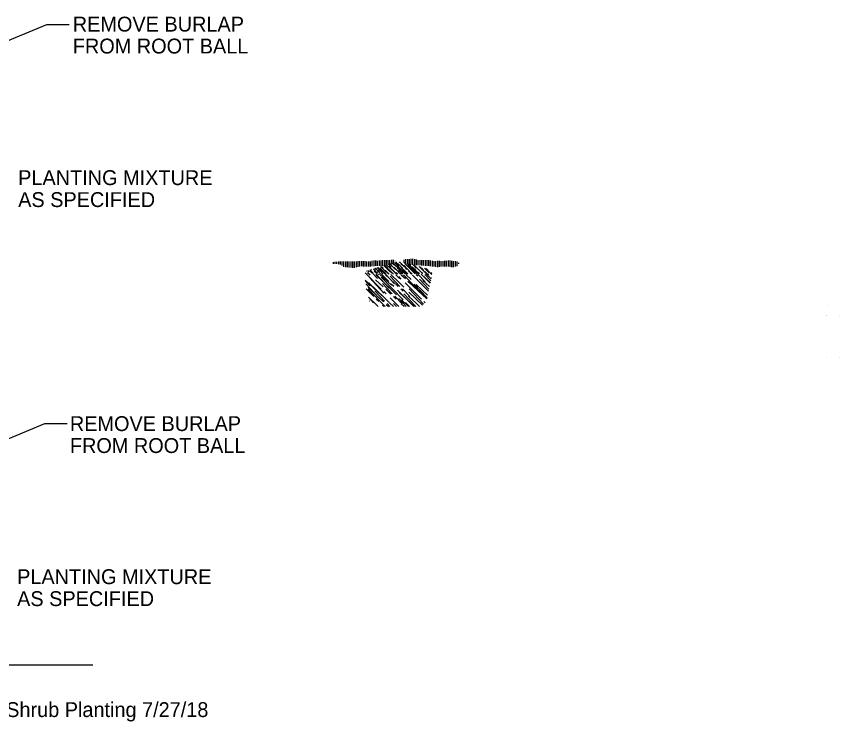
# Model space of a CAD drawing. Extents: x 10082 to 10186, y 10014 to 10052.
# Drawn here: x 10147.41 to 10186.18, y 10014.37 to 10047.58 of the extents above; entities that cross this region are included whole.
import ezdxf

# ---------------------------------------------------------------- set-up
doc = ezdxf.new("R2010")
doc.units = 0
for name, color, linetype in [('Default', 7, 'Continuous'), ('G-ANNO-CELL', 7, 'Continuous'), ('G-ANNO-TEXT', 7, 'Continuous'), ('G-DETL-TEXT', 7, 'Continuous')]:
    doc.layers.add(name, color=color, linetype=linetype)

# ---------------------------------------------------------------- blocks, each defined once
blk = doc.blocks.new('POINT_DISPLAY')
at = {"layer": 'Default'}
blk.add_line((0, 0), (0, 0), dxfattribs=at)
blk = doc.blocks.new('_X3')
at = {"layer": 'Default'}
for p, q in [((2.0243, 1.2759), (2.0002, 1.3001)), ((2.0038, 1.3007), (2.0077, 1.2971)), ((2.0067, 1.2931), (2.0283, 1.2699)), ((2.0187, 1.2918), (2.0118, 1.2989)), ((2.0159, 1.2987), (2.036, 1.2771)), ((2.0394, 1.2747), (2.0166, 1.2967)), ((2.0196, 1.2985), (2.0203, 1.2977)), ((2.0396, 1.2817), (2.0218, 1.2983)), ((2.024, 1.2939), (2.0571, 1.2597)), ((2.0355, 1.2872), (2.0245, 1.2982)), ((2.0301, 1.2979), (2.0378, 1.2907)), ((2.0312, 1.2978), (2.0438, 1.2843)), ((2.0521, 1.2799), (2.0374, 1.2952)), ((2.0504, 1.2861), (2.0386, 1.2975)), ((2.0462, 1.2973), (2.0515, 1.2916)), ((2.0542, 1.2909), (2.0505, 1.2947)), ((2.054, 1.2972), (2.054, 1.2973)), ((2.0541, 1.2973), (2.0603, 1.2915)), ((2.0636, 1.291), (2.0574, 1.2973)), ((2.0575, 1.2973), (2.0761, 1.2781)), ((2.0691, 1.2902), (2.0616, 1.2974)), ((2.0949, 1.2727), (2.0711, 1.2965)), ((2.0766, 1.2979), (2.0788, 1.2959)), ((2.0897, 1.2868), (2.0788, 1.2981)), ((2.0977, 1.2854), (2.0838, 1.2984)), ((2.0975, 1.2848), (2.0877, 1.2942)), ((2.0892, 1.2977), (2.0982, 1.288)), ((2.0989, 1.2911), (2.0913, 1.2988)), ((2.0928, 1.2989), (2.0951, 1.2964)), ((2.0974, 1.3003), (2.0999, 1.298)), ((2.0999, 1.2991), (2.0982, 1.3008)), ((2.0988, 1.2926), (2.0992, 1.2923)), ((2.0252, 1.2662), (2.0003, 1.2894)), ((2.0073, 1.2807), (2.0005, 1.2877)), ((2.001, 1.2837), (2.0206, 1.2627)), ((2.0284, 1.2633), (2.0055, 1.2853)), ((2.0154, 1.2899), (2.027, 1.2791)), ((2.0407, 1.2689), (2.026, 1.2841)), ((2.043, 1.2797), (2.0393, 1.2834)), ((2.0417, 1.2871), (2.0494, 1.2799)), ((2.0581, 1.2788), (2.0504, 1.2861)), ((2.0842, 1.261), (2.0598, 1.2853)), ((2.0641, 1.2879), (2.068, 1.2843)), ((2.0924, 1.2614), (2.0656, 1.2864)), ((2.0783, 1.2757), (2.0672, 1.2872)), ((2.0737, 1.2833), (2.0927, 1.2629)), ((2.0935, 1.2666), (2.0767, 1.2828)), ((2.0814, 1.2905), (2.0955, 1.2755)), ((2.0866, 1.2886), (2.0964, 1.2795)), ((2.0131, 1.2647), (2.0018, 1.276)), ((2.0046, 1.2783), (2.0162, 1.2675)), ((2.0049, 1.2756), (2.0299, 1.2497)), ((2.0293, 1.2579), (2.0146, 1.2731)), ((2.0318, 1.2685), (2.028, 1.2722)), ((2.0309, 1.2755), (2.0386, 1.2683)), ((2.047, 1.2673), (2.0394, 1.2747)), ((2.0729, 1.2498), (2.0486, 1.2741)), ((2.0738, 1.2498), (2.0512, 1.2709)), ((2.0533, 1.2763), (2.0572, 1.2726)), ((2.0669, 1.2647), (2.0558, 1.2761)), ((2.0582, 1.2689), (2.076, 1.2498)), ((2.086, 1.2518), (2.0657, 1.2714)), ((2.066, 1.2761), (2.0874, 1.2531)), ((2.0758, 1.277), (2.0874, 1.2662)), ((2.0798, 1.2743), (2.0923, 1.2612)), ((2.0923, 1.2612), (2.0856, 1.2681)), ((2.005, 1.2639), (2.0128, 1.2555)), ((2.0174, 1.2519), (2.005, 1.2638)), ((2.0073, 1.2578), (2.0069, 1.2583)), ((2.0206, 1.2572), (2.0168, 1.261)), ((2.0201, 1.2639), (2.0278, 1.2566)), ((2.036, 1.2559), (2.0284, 1.2633)), ((2.0505, 1.2498), (2.0374, 1.2628)), ((2.0425, 1.2646), (2.0464, 1.261)), ((2.0554, 1.2537), (2.0444, 1.2651)), ((2.0505, 1.2616), (2.0615, 1.2498)), ((2.0652, 1.2498), (2.0546, 1.26)), ((2.0607, 1.2559), (2.0666, 1.2498)), ((2.0649, 1.2654), (2.0765, 1.2546)), ((2.0812, 1.2499), (2.0742, 1.2571)), ((2.0897, 1.2554), (2.0879, 1.2572)), ((2.0912, 1.2626), (2.0924, 1.2615)), ((2.0196, 1.2497), (2.0174, 1.2519)), ((2.0281, 1.2497), (2.0262, 1.2516)), ((2.0317, 1.253), (2.0352, 1.2497)), ((2.0372, 1.2497), (2.033, 1.2541)), ((2.0428, 1.2497), (2.0368, 1.2554)), ((2.0427, 1.2544), (2.0471, 1.2498)), ((2.0541, 1.2538), (2.0584, 1.2498)), ((2.0804, 1.251), (2.0816, 1.2499))]:
    blk.add_line(p, q, dxfattribs=at)
blk = doc.blocks.new('_X2')
at = {"layer": 'Default'}
for p, q in [((2.0585, 1.3154), (2.0585, 1.3196)), ((2.0611, 1.3149), (2.0611, 1.3205)), ((2.0638, 1.3143), (2.0638, 1.3207)), ((2.0664, 1.3134), (2.0664, 1.3208)), ((2.069, 1.3127), (2.069, 1.3209)), ((2.0717, 1.3123), (2.0717, 1.321)), ((2.0743, 1.3119), (2.0743, 1.3205)), ((2.077, 1.3115), (2.077, 1.3199)), ((2.0796, 1.3115), (2.0796, 1.3193)), ((2.0823, 1.3115), (2.0823, 1.319)), ((2.0849, 1.3113), (2.0849, 1.3191)), ((2.0876, 1.3111), (2.0876, 1.3192)), ((2.0902, 1.3108), (2.0902, 1.3193)), ((2.0929, 1.3106), (2.0929, 1.3191)), ((2.0955, 1.3104), (2.0955, 1.319)), ((2.0981, 1.3101), (2.0981, 1.3186)), ((2.1008, 1.3098), (2.1008, 1.318)), ((2.1034, 1.3095), (2.1034, 1.3175)), ((2.1061, 1.3091), (2.1061, 1.3178)), ((2.1087, 1.3088), (2.1087, 1.3181)), ((2.1114, 1.3091), (2.1114, 1.3181)), ((2.114, 1.3097), (2.114, 1.3178)), ((2.1167, 1.3098), (2.1167, 1.3175)), ((2.1193, 1.3098), (2.1193, 1.3179)), ((2.122, 1.3098), (2.122, 1.3183)), ((2.1246, 1.3097), (2.1246, 1.3186)), ((2.1273, 1.3092), (2.1273, 1.3184)), ((2.1299, 1.3087), (2.1299, 1.3183)), ((2.1325, 1.3086), (2.1325, 1.3178)), ((2.1352, 1.3094), (2.1352, 1.3174)), ((2.1378, 1.3103), (2.1378, 1.317)), ((2.1405, 1.3135), (2.1405, 1.3151))]:
    blk.add_line(p, q, dxfattribs=at)
blk = doc.blocks.new('_X1')
at = {"layer": 'Default'}
for p, q in [((1.9632, 1.3126), (1.9632, 1.3172)), ((1.9659, 1.3109), (1.9659, 1.3172)), ((1.9685, 1.309), (1.9685, 1.3172)), ((1.9711, 1.3086), (1.9711, 1.3172)), ((1.9844, 1.3078), (1.9844, 1.3172)), ((1.987, 1.3085), (1.987, 1.3173)), ((1.9897, 1.3091), (1.9897, 1.3175)), ((1.9923, 1.3098), (1.9923, 1.3175)), ((1.995, 1.31), (1.995, 1.3175)), ((1.9976, 1.3097), (1.9976, 1.3175)), ((2.0003, 1.3095), (2.0003, 1.3174)), ((2.0029, 1.3095), (2.0029, 1.3173)), ((2.0055, 1.3096), (2.0055, 1.3173)), ((2.0082, 1.3097), (2.0082, 1.3172)), ((2.0108, 1.31), (2.0108, 1.3179)), ((2.0135, 1.3103), (2.0135, 1.3185)), ((2.0161, 1.3106), (2.0161, 1.3185)), ((2.0188, 1.3107), (2.0188, 1.3183)), ((2.0214, 1.3104), (2.0214, 1.3184)), ((2.0241, 1.3101), (2.0241, 1.3186)), ((2.0267, 1.3108), (2.0267, 1.3189)), ((2.0294, 1.3115), (2.0294, 1.3192)), ((2.032, 1.312), (2.032, 1.3191)), ((2.0346, 1.3125), (2.0346, 1.319)), ((2.0373, 1.3129), (2.0373, 1.3192)), ((2.0399, 1.3141), (2.0399, 1.3197)), ((2.0426, 1.3153), (2.0426, 1.3195)), ((2.0452, 1.3178), (2.0452, 1.3183)), ((1.9526, 1.3137), (1.9526, 1.3163)), ((1.9553, 1.3137), (1.9553, 1.3165)), ((1.9579, 1.3135), (1.9579, 1.3167)), ((1.9606, 1.313), (1.9606, 1.3169)), ((1.9738, 1.3084), (1.9738, 1.3171)), ((1.9764, 1.3082), (1.9764, 1.317)), ((1.9791, 1.308), (1.9791, 1.3169)), ((1.9817, 1.3078), (1.9817, 1.317))]:
    blk.add_line(p, q, dxfattribs=at)
blk = doc.blocks.new('_X0')
at = {"layer": 'Default'}
for p, q in [((0.6297, 0.3389), (0.6229, 0.3453)), ((0.6231, 0.345), (0.6397, 0.3279)), ((0.6263, 0.3442), (0.6249, 0.3455)), ((0.6256, 0.3456), (0.6259, 0.3452)), ((0.63, 0.346), (0.6307, 0.3454)), ((0.638, 0.3386), (0.6306, 0.346)), ((0.641, 0.3417), (0.6376, 0.3452)), ((0.5815, 0.3323), (0.5811, 0.3327)), ((0.5851, 0.331), (0.583, 0.3332)), ((0.5911, 0.3294), (0.5862, 0.3342)), ((0.5862, 0.3326), (0.5894, 0.3296)), ((0.5887, 0.3338), (0.5877, 0.3347)), ((0.5941, 0.3332), (0.5915, 0.3358)), ((0.5918, 0.3352), (0.5978, 0.3288)), ((0.5964, 0.3289), (0.5928, 0.3324)), ((0.5936, 0.3365), (0.5955, 0.3348)), ((0.5944, 0.3367), (0.6023, 0.3285)), ((0.5968, 0.3349), (0.5949, 0.3368)), ((0.597, 0.3375), (0.6056, 0.3282)), ((0.5974, 0.333), (0.5993, 0.3312)), ((0.6087, 0.3281), (0.5985, 0.3379)), ((0.6006, 0.3311), (0.5987, 0.333)), ((0.6072, 0.3311), (0.6016, 0.3368)), ((0.6104, 0.328), (0.6017, 0.3361)), ((0.6026, 0.3392), (0.6104, 0.3308)), ((0.6028, 0.3388), (0.6047, 0.337)), ((0.6062, 0.3368), (0.6043, 0.3386)), ((0.6152, 0.3328), (0.6072, 0.3405)), ((0.6083, 0.3409), (0.6143, 0.3344)), ((0.6129, 0.3366), (0.6086, 0.341)), ((0.6086, 0.341), (0.6118, 0.3377)), ((0.6086, 0.3334), (0.6144, 0.328)), ((0.6151, 0.3278), (0.609, 0.334)), ((0.6225, 0.3312), (0.6112, 0.3417)), ((0.6136, 0.3358), (0.6215, 0.3277)), ((0.6139, 0.3426), (0.6181, 0.338)), ((0.614, 0.3392), (0.6198, 0.3338)), ((0.6265, 0.3276), (0.6146, 0.3396)), ((0.619, 0.3291), (0.6152, 0.3328)), ((0.6207, 0.3385), (0.6159, 0.3432)), ((0.6214, 0.3277), (0.6165, 0.3328)), ((0.6186, 0.3421), (0.6172, 0.3435)), ((0.6196, 0.3443), (0.622, 0.3416)), ((0.62, 0.3444), (0.6252, 0.3396)), ((0.6324, 0.333), (0.6207, 0.3446)), ((0.6246, 0.3348), (0.6207, 0.3385)), ((0.6296, 0.3307), (0.6222, 0.3383)), ((0.6301, 0.3405), (0.6263, 0.3442)), ((0.6272, 0.3378), (0.631, 0.3341)), ((0.6353, 0.3362), (0.628, 0.3438)), ((0.6292, 0.3339), (0.6351, 0.3276)), ((0.6326, 0.3436), (0.6365, 0.34)), ((0.6331, 0.3375), (0.6422, 0.3278)), ((0.6432, 0.3278), (0.6339, 0.3368)), ((0.6417, 0.3277), (0.6355, 0.3335)), ((0.637, 0.3411), (0.6478, 0.3295)), ((0.6427, 0.3286), (0.6371, 0.3343)), ((0.6384, 0.3381), (0.6403, 0.3363)), ((0.6508, 0.3315), (0.6394, 0.3425)), ((0.6417, 0.3349), (0.6398, 0.3368)), ((0.6413, 0.3442), (0.6517, 0.3331)), ((0.6427, 0.3438), (0.6492, 0.3371)), ((0.6563, 0.3286), (0.6428, 0.3413)), ((0.6484, 0.3341), (0.6429, 0.3398)), ((0.6442, 0.3327), (0.6492, 0.3281)), ((0.6445, 0.3433), (0.6457, 0.3421)), ((0.6473, 0.3405), (0.6455, 0.3424)), ((0.6496, 0.3385), (0.6554, 0.3331)), ((0.6593, 0.3285), (0.6501, 0.3377)), ((0.651, 0.3352), (0.6575, 0.3284)), ((0.6511, 0.3415), (0.6555, 0.3367)), ((0.6563, 0.3372), (0.6523, 0.3412)), ((0.6541, 0.3396), (0.6527, 0.341)), ((0.6601, 0.3336), (0.6563, 0.3372)), ((0.6647, 0.3286), (0.6578, 0.3358)), ((0.6679, 0.3311), (0.6601, 0.339)), ((0.6635, 0.3364), (0.661, 0.3387)), ((0.6628, 0.3371), (0.6666, 0.3335)), ((0.6666, 0.3326), (0.6702, 0.3288)), ((0.6708, 0.3337), (0.6678, 0.3368)), ((0.6678, 0.3368), (0.6748, 0.3296)), ((0.6753, 0.33), (0.6695, 0.3356)), ((0.6706, 0.336), (0.6759, 0.3304)), ((0.588, 0.3316), (0.5899, 0.3295)), ((0.5983, 0.3288), (0.5959, 0.3313)), ((0.6034, 0.3283), (0.6034, 0.3283)), ((0.6218, 0.332), (0.6256, 0.3283)), ((0.6254, 0.3303), (0.6278, 0.3276)), ((0.632, 0.3276), (0.6284, 0.3311)), ((0.6326, 0.3276), (0.6314, 0.3288)), ((0.633, 0.3323), (0.6349, 0.3305)), ((0.6361, 0.3293), (0.6342, 0.3311)), ((0.6486, 0.328), (0.6445, 0.3321)), ((0.6542, 0.3283), (0.6508, 0.3315)), ((0.654, 0.3283), (0.652, 0.3303)), ((0.6574, 0.3313), (0.6603, 0.3286)), ((0.6628, 0.329), (0.6631, 0.3286)), ((0.6652, 0.3286), (0.6639, 0.3299)), ((0.6686, 0.3317), (0.6705, 0.3299)), ((0.6715, 0.3289), (0.6693, 0.331)), ((0.6702, 0.3288), (0.6698, 0.3293)), ((0.6748, 0.3296), (0.6727, 0.3318))]:
    blk.add_line(p, q, dxfattribs=at)

msp = doc.modelspace()

# ---------------------------------------------------------------- linework, layer by layer
at = {"layer": 'Default'}
for p, q in [((10148.826, 10047.185), (10138.6, 10042.964)), ((10149.897, 10047.185), (10148.826, 10047.185)), ((10148.734, 10028.388), (10138.509, 10024.167)), ((10149.805, 10028.388), (10148.734, 10028.388))]:
    msp.add_line(p, q, dxfattribs=at)
at = {"layer": 'G-ANNO-TEXT'}
msp.add_line((10122.114, 10017.044), (10151.008, 10017.044), dxfattribs=at)

# ---------------------------------------------------------------- block references
at = {"layer": 'Default', "xscale": 31.496062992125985, "yscale": 31.496062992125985}
for name, p in [('_X1', (10100.837, 9994.556)), ('_X0', (10145.594, 10025.119)), ('_X2', (10100.837, 9994.556)), ('_X3', (10100.837, 9994.556)), ('POINT_DISPLAY', (10166.894, 10035.483)), ('POINT_DISPLAY', (10185.59, 10033.966)), ('POINT_DISPLAY', (10185.564, 10033.491)), ('POINT_DISPLAY', (10185.564, 10033.479)), ('POINT_DISPLAY', (10186.165, 10033.479)), ('POINT_DISPLAY', (10185.564, 10031.538)), ('POINT_DISPLAY', (10186.179, 10031.538))]:
    msp.add_blockref(name, p, dxfattribs=at)

# ---------------------------------------------------------------- texts
at = {"layer": 'G-ANNO-CELL'}
msp.add_text('MD 329300 003 Shrub Planting 7/27/18', height=0.7, dxfattribs=at).set_placement((10140.005, 10014.585))
at = {"layer": 'G-DETL-TEXT'}
for s, p in [('REMOVE BURLAP ', (10150.063, 10046.868)), ('FROM ROOT BALL', (10150.063, 10045.835)), ('PLANTING MIXTURE ', (10147.49, 10039.638)), ('AS SPECIFIED', (10147.49, 10038.604)), ('REMOVE BURLAP ', (10149.926, 10028.054)), ('FROM ROOT BALL', (10149.926, 10027.021)), ('PLANTING MIXTURE ', (10147.44, 10020.845)), ('AS SPECIFIED', (10147.44, 10019.811))]:
    msp.add_text(s, height=0.7, dxfattribs=at).set_placement(p)

doc.saveas('drawing.dxf')
